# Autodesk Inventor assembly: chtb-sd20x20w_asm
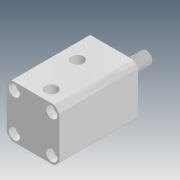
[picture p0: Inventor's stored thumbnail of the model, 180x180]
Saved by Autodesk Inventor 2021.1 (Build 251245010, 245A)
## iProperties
Company: Microsoft
Created: 2018-05
Part Number: chtb-sd20x20w_asm
Description: STEP AP214
Document SubType Name: Assembly
Designer: user
Title: chtb-sd20x20w_asm.STEP
Author: Windows
Revision Number: ÈÎºÎ
Sending System: SolidWorks 2015
Preprocessor: SwSTEP 2.0
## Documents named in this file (4)
- D:\Vault_2016\Projekty\Clamptek\Hydraulic\CHTB\CHTB-20\Inventor\CHTB-SD20x20W\chtb-sd20x20w_asm.iam
- D:\Vault_2016\Projekty\Clamptek\Hydraulic\CHTB\CHTB-20\Inventor\CHTB-SD20x20W\CHTB-SD20X20NBT.ipt
- D:\Vault_2016\Projekty\Clamptek\Hydraulic\CHTB\CHTB-20\Inventor\CHTB-SD20x20W\CHTB-SD20X20WHSG.ipt
- D:\Vault_2016\Projekty\Clamptek\Hydraulic\CHTB\CHTB-20\Inventor\CHTB-SD20x20W\QG.ipt
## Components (3 placed, 3 different names)
1. CHTB-SD20X20NBT_1
2. CHTB-SD20X20WHSG_2
3. QG_3
